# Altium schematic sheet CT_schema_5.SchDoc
size 517 x 390 mm
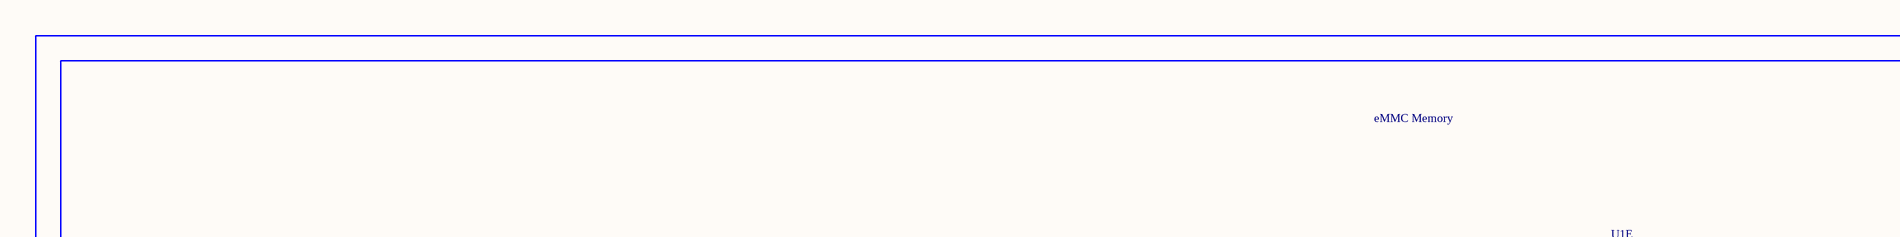
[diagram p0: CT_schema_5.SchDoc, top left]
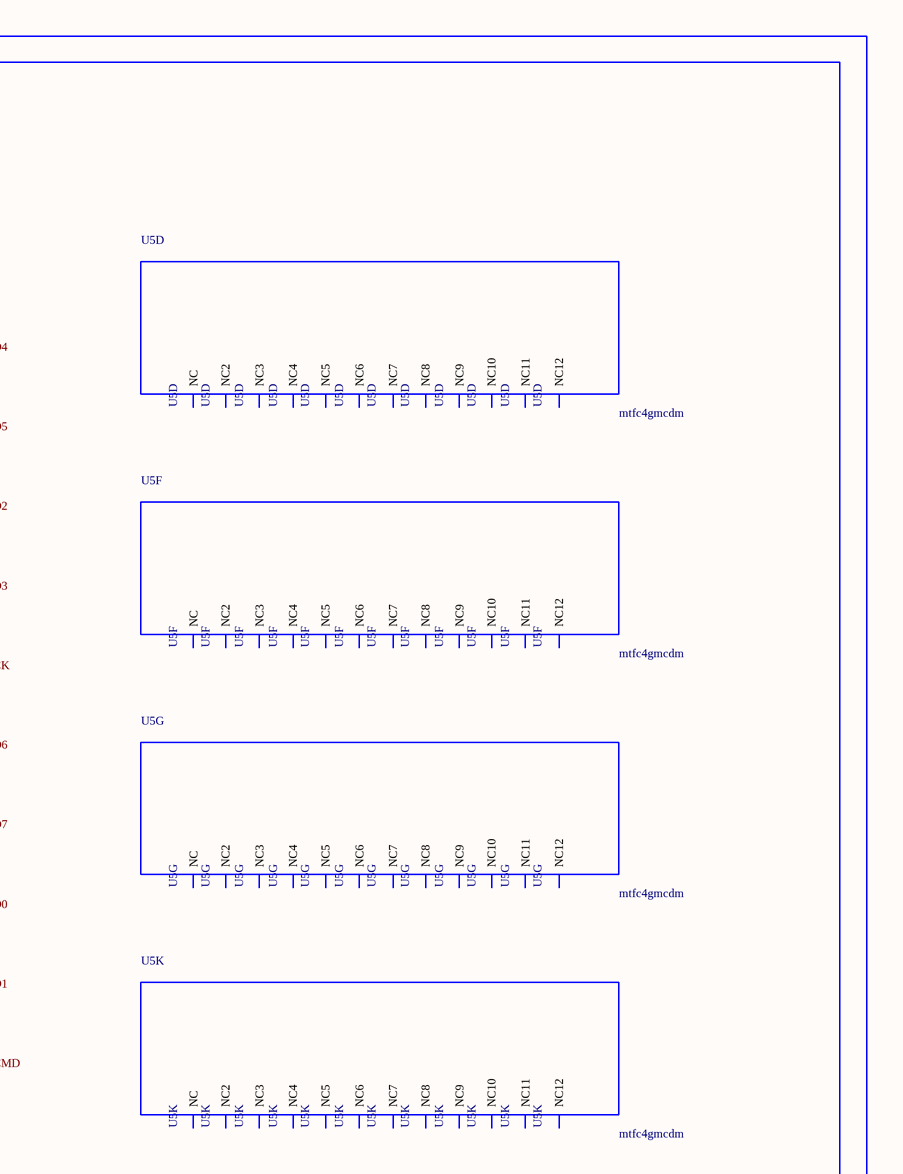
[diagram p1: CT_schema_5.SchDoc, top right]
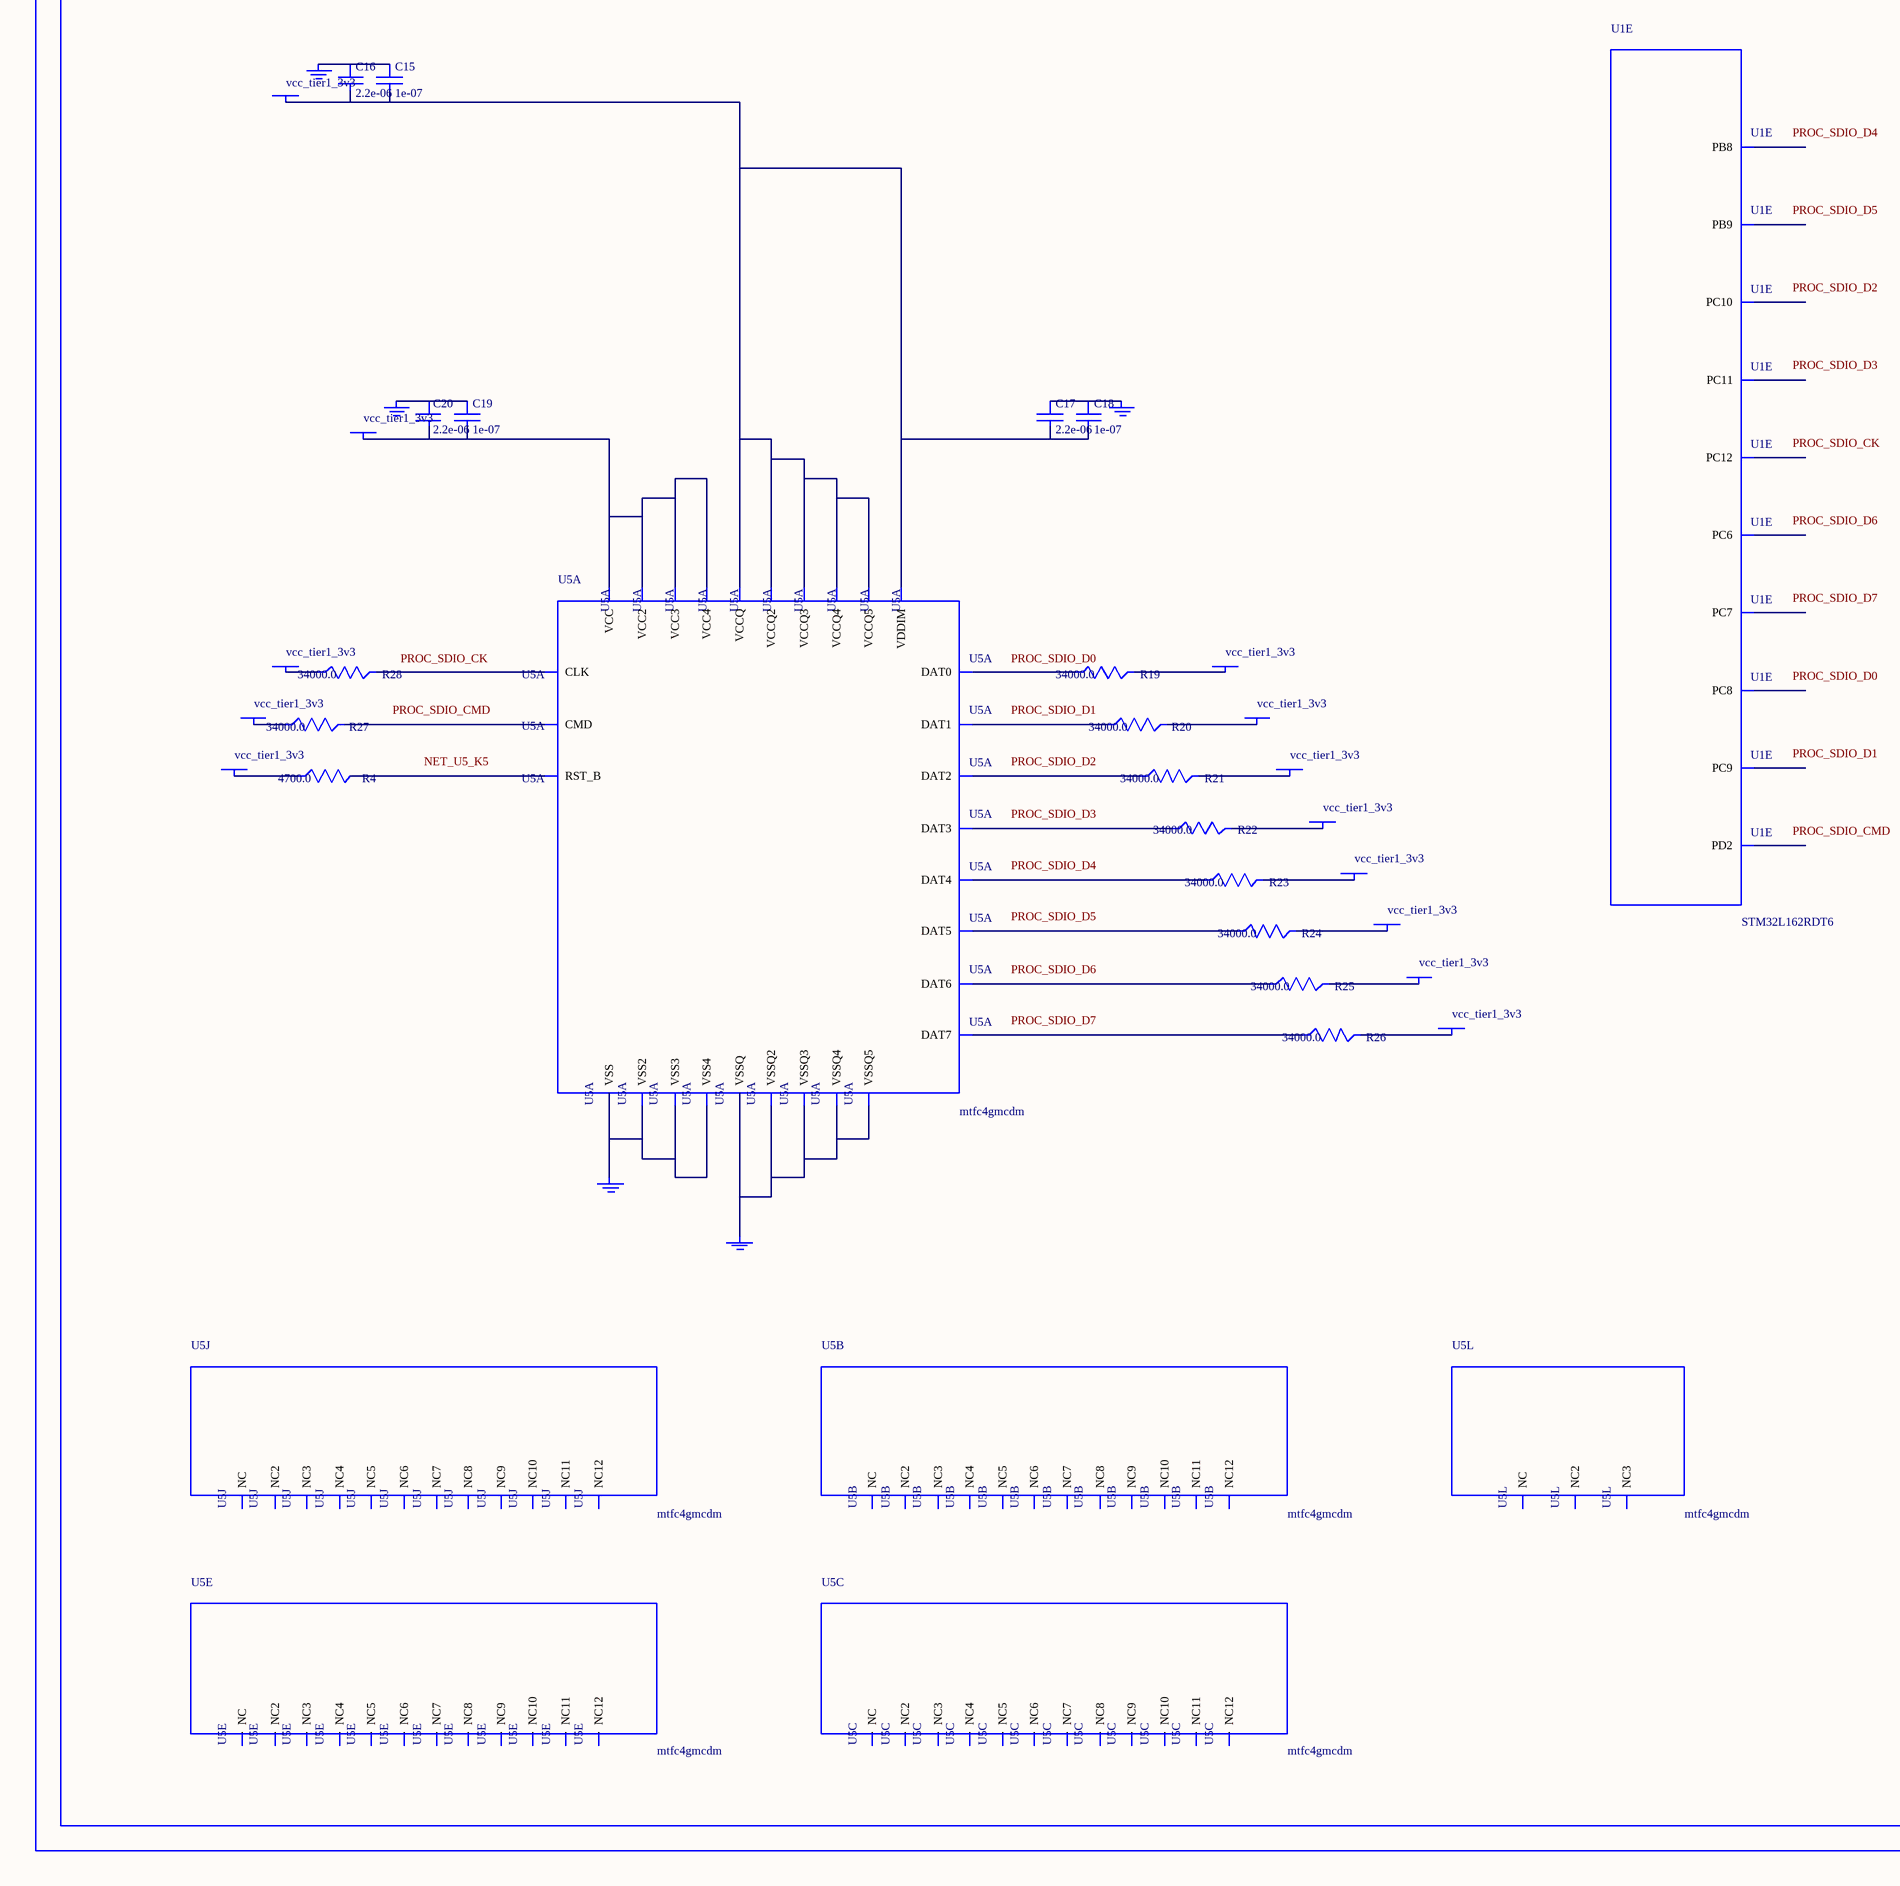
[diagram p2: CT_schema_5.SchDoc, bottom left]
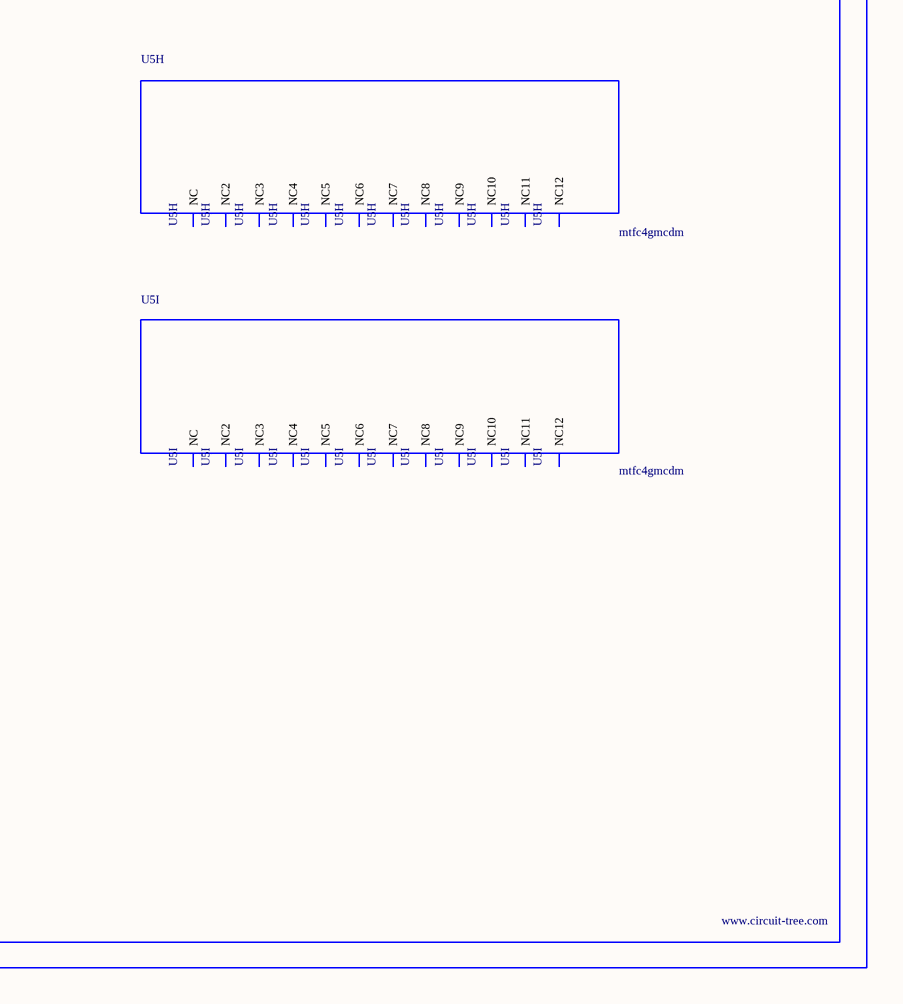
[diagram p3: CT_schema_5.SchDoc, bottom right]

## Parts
BORDER4  (no value)
C15  1e-07  [C0402]
C16  2.2e-06  [C0603]
C17  2.2e-06  [C0603]
C18  1e-07  [C0402]
C19  1e-07  [C0402]
C20  2.2e-06  [C0603]
GND_INSTANCE_4_0  (no value)
GND_INSTANCE_4_1  (no value)
GND_INSTANCE_4_2  (no value)
GND_INSTANCE_4_3  (no value)
GND_INSTANCE_4_4  (no value)
POWER_INSTANCE_4_0  vcc_tier1_3v3
POWER_INSTANCE_4_1  vcc_tier1_3v3
POWER_INSTANCE_4_2  vcc_tier1_3v3
POWER_INSTANCE_4_3  vcc_tier1_3v3
POWER_INSTANCE_4_4  vcc_tier1_3v3
POWER_INSTANCE_4_5  vcc_tier1_3v3
POWER_INSTANCE_4_6  vcc_tier1_3v3
POWER_INSTANCE_4_7  vcc_tier1_3v3
POWER_INSTANCE_4_8  vcc_tier1_3v3
POWER_INSTANCE_4_9  vcc_tier1_3v3
POWER_INSTANCE_4_10  vcc_tier1_3v3
POWER_INSTANCE_4_11  vcc_tier1_3v3
POWER_INSTANCE_4_12  vcc_tier1_3v3
R4  4700.0  [R0603]
R19  34000.0  [R0603]
R20  34000.0  [R0603]
R21  34000.0  [R0603]
R22  34000.0  [R0603]
R23  34000.0  [R0603]
R24  34000.0  [R0603]
R25  34000.0  [R0603]
R26  34000.0  [R0603]
R27  34000.0  [R0603]
R28  34000.0  [R0603]
U1  STM32L162RDT6  [LQFP64]  (part E of 5)
U5  mtfc4gmcdm  [TFBGA-153]  (parts A,B,C,D,E,F,G,H,I,J,K,L of 12)

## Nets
NetC15_1: C15.1 C16.1 GND_INSTANCE_4_0.0(GND)
NetC15_2: C15.2 C16.2 C17.2 C18.2 POWER_INSTANCE_4_0.0(PWR) U5.C2(VDDIM) U5.C6(VCCQ) U5.M4(VCCQ2) U5.N4(VCCQ3) U5.P3(VCCQ4) U5.P5(VCCQ5)
NetC17_1: C17.1 C18.1 GND_INSTANCE_4_1.0(GND)
NetC19_1: C19.1 C20.1 GND_INSTANCE_4_2.0(GND)
NetC19_2: C19.2 C20.2 POWER_INSTANCE_4_1.0(PWR) U5.E6(VCC) U5.F5(VCC2) U5.J10(VCC3) U5.K9(VCC4)
NetGND_INSTANCE_4_3_0: GND_INSTANCE_4_3.0(GND) U5.E7(VSS) U5.G5(VSS2) U5.H10(VSS3) U5.K8(VSS4)
NetGND_INSTANCE_4_4_0: GND_INSTANCE_4_4.0(GND) U5.C4(VSSQ) U5.N2(VSSQ2) U5.N5(VSSQ3) U5.P4(VSSQ4) U5.P6(VSSQ5)
NetPOWER_INSTANCE_4_2_0: POWER_INSTANCE_4_2.0(PWR) R19.2
NetPOWER_INSTANCE_4_3_0: POWER_INSTANCE_4_3.0(PWR) R20.2
NetPOWER_INSTANCE_4_4_0: POWER_INSTANCE_4_4.0(PWR) R21.2
NetPOWER_INSTANCE_4_5_0: POWER_INSTANCE_4_5.0(PWR) R22.2
NetPOWER_INSTANCE_4_6_0: POWER_INSTANCE_4_6.0(PWR) R23.2
NetPOWER_INSTANCE_4_7_0: POWER_INSTANCE_4_7.0(PWR) R24.2
NetPOWER_INSTANCE_4_8_0: POWER_INSTANCE_4_8.0(PWR) R25.2
NetPOWER_INSTANCE_4_9_0: POWER_INSTANCE_4_9.0(PWR) R26.2
NetPOWER_INSTANCE_4_10_0: POWER_INSTANCE_4_10.0(PWR) R27.1
NetPOWER_INSTANCE_4_11_0: POWER_INSTANCE_4_11.0(PWR) R28.1
NetPOWER_INSTANCE_4_12_0: POWER_INSTANCE_4_12.0(PWR) R4.1
NetR4_2: R4.2 U5.K5(RST_B)
NetR19_1: R19.1 U5.A3(DAT0)
NetR20_1: R20.1 U5.A4(DAT1)
NetR21_1: R21.1 U5.A5(DAT2)
NetR22_1: R22.1 U5.B2(DAT3)
NetR23_1: R23.1 U5.B3(DAT4)
NetR24_1: R24.1 U5.B4(DAT5)
NetR25_1: R25.1 U5.B5(DAT6)
NetR26_1: R26.1 U5.B6(DAT7)
NetR27_2: R27.2 U5.M5(CMD)
NetR28_2: R28.2 U5.M6(CLK)

Not connected (* = marked no-connect by the designer): U1 37(PC6) 38(PC7) 39(PC8) 40(PC9) 51(PC10) 52(PC11) 53(PC12) 54(PD2) 61(PB8) 62(PB9); U5 A1(NC) A2(NC7) A6(NC8) A7(NC9) A8(NC10) A9(NC11) A10(NC2) A11(NC3) A12(NC4) A13(NC5) A14(NC6) B1(NC12) B7(NC6) B8(NC7) B9(NC8) B10(NC) B11(NC2) B12(NC3) B13(NC4) B14(NC5) C1(NC9) C3(NC10) C5(NC11) C7(NC12) C8(NC6) C9(NC7) C10(NC) C11(NC2) C12(NC3) C13(NC4) C14(NC5) D1(NC8) D2(NC10) D3(NC11) D4(NC12) D12(NC9) D13(NC) D14(NC2) E1(NC3) E2(NC8) E3(NC9) E5(NC10) E8(NC11) E9(NC12) E10(NC4) E12(NC5) E13(NC6) E14(NC7) F1(NC) F2(NC6) F3(NC7) F10(NC2) F12(NC3) F13(NC4) F14(NC5) G1(NC8) G2(NC11) G3(NC12) G10(NC9) G12(NC10) G13(NC) G14(NC2) H1(NC3) H2(NC7) H3(NC8) H5(NC9) H12(NC4) H13(NC5) H14(NC6) J1(NC10) J2(NC11) J3(NC12) J5(NC4) J12(NC) J13(NC2) J14(NC3) K1(NC5) K2(NC9) K3(NC10) K6(NC11) K7(NC12) K10(NC6) K12(NC7) K13(NC8) K14(NC) L1(NC2) L2(NC6) L3(NC7) L12(NC3) L13(NC4) L14(NC5) M1(NC8) M2(NC9) M3(NC10) M7(NC11) M8(NC12) M9(NC6) M10(NC) M11(NC2) M12(NC3) M13(NC4) M14(NC5) N1(NC7) N3(NC8) N6(NC9) N7(NC10) N8(NC11) N9(NC12) N10(NC) N11(NC2) N12(NC3) N13(NC4) N14(NC5) P1(NC6) P2(NC9) P7(NC10) P8(NC11) P9(NC12) P10(NC7) P11(NC8) P12(NC) P13(NC2) P14(NC3)

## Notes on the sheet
- Labels drawn without touching a wire or pin: NET_U5_K5, PROC_SDIO_CK, PROC_SDIO_CMD, PROC_SDIO_D0, PROC_SDIO_D1, PROC_SDIO_D2, PROC_SDIO_D3, PROC_SDIO_D4, PROC_SDIO_D5, PROC_SDIO_D6, PROC_SDIO_D7

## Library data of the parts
BORDER4 = BORDER_PAGE4
C15 C18 C19 = C0402C104K3RACTU
C16 C17 C20 = C0603C225K8RACTU
GND_INSTANCE_4_0-GND_INSTANCE_4_4 = GND
POWER_INSTANCE_4_0-POWER_INSTANCE_4_12 = PWR
R4 = RC0603JR-074K7L
R19-R28 = ERA3ARB3402V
